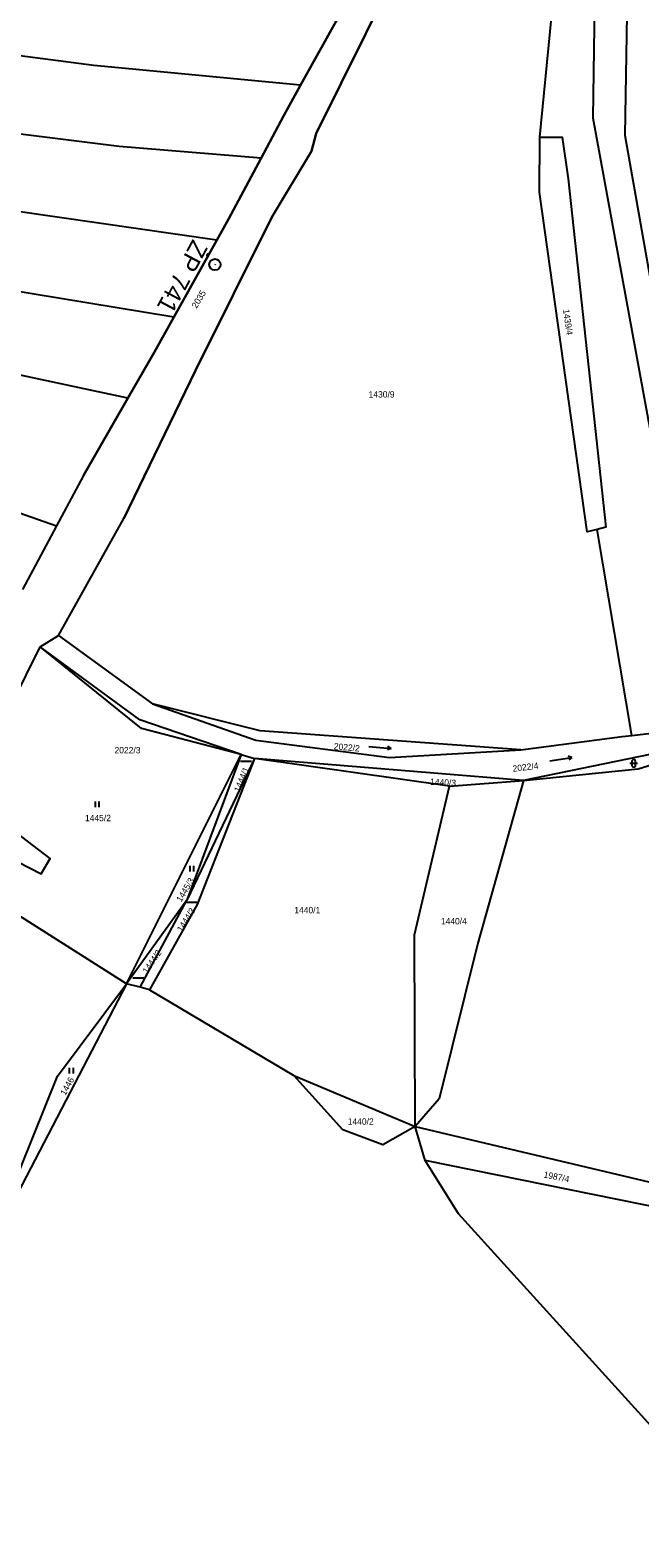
# Model space of a CAD drawing. Extents: x -793666 to -785424, y -1118958 to -1108761.
# Drawn here: x -787242.9 to -787079.7, y -1118708.9 to -1118305 of the extents above; entities that cross this region are included whole.
import ezdxf

# ---------------------------------------------------------------- set-up
doc = ezdxf.new("R2010")
doc.units = 0
for name, color, linetype in [('Hranice parcel', 7, 'Continuous'), ('Parcelní čísla', 7, 'Continuous'), ('Vrstva 53', 7, 'Continuous'), ('Vrstva 63', 7, 'Continuous'), ('Značky kultur', 7, 'Continuous')]:
    doc.layers.add(name, color=color, linetype=linetype)

msp = doc.modelspace()

# ---------------------------------------------------------------- linework, layer by layer
at = {"layer": 'Hranice parcel'}
for p, q in [((-787160.15, -1118301.02), (-787170.53, -1118319.75)), ((-787192.93, -1118361.27), (-787204.45, -1118381.96)), ((-787235.84, -1118437.8), (-787245.01, -1118454.92)), ((-787081.87, -1118493.99), (-787091.16, -1118438.76)), ((-787240.28, -1118470.25), (-787235.39, -1118467.18)), ((-787235.39, -1118467.18), (-787210.21, -1118485.49)), ((-787081.87, -1118493.99), (-787062.37, -1118491.63)), ((-787053.4, -1118494.16), (-787110.85, -1118506.06)), ((-787217.11, -1118560.49), (-787186.43, -1118499.08)), ((-787186.43, -1118499.08), (-787200.96, -1118538.1)), ((-787182.84, -1118500.19), (-787200.96, -1118538.1)), ((-787186.43, -1118499.08), (-787182.84, -1118500.19)), ((-787110.85, -1118506.06), (-787182.84, -1118500.19)), ((-787130.65, -1118507.57), (-787182.84, -1118500.19)), ((-787130.65, -1118507.57), (-787110.85, -1118506.06)), ((-787200.96, -1118538.1), (-787217.11, -1118560.49)), ((-787213.48, -1118561.45), (-787200.96, -1118538.1)), ((-787217.11, -1118560.49), (-787255.19, -1118633.7)), ((-787213.48, -1118561.45), (-787217.11, -1118560.49)), ((-787210.97, -1118562.12), (-787213.48, -1118561.45)), ((-787210.97, -1118562.12), (-787172.32, -1118585.11)), ((-787172.32, -1118585.11), (-787139.82, -1118598.75)), ((-787139.82, -1118598.75), (-787071.98, -1118614.82)), ((-787137.18, -1118607.84), (-787139.82, -1118598.75)), ((-787072.89, -1118620.93), (-787137.18, -1118607.84)), ((-787128.21, -1118622.13), (-787137.18, -1118607.84))]:
    msp.add_line(p, q, dxfattribs=at)
for points in [[(-787177.84, -1117853.72), (-787161.21, -1117872.93), (-787128.04, -1117934.59), (-787083.58, -1118004.78), (-787073.62, -1118057.71), (-787080.45, -1118134.14), (-787083.67, -1118333.2), (-787055.86, -1118490.84)], [(-787163.99, -1117893.46), (-787091.23, -1118006.46), (-787082.09, -1118056.11), (-787089.51, -1118139.72), (-787092.27, -1118328.55), (-787062.37, -1118491.63)], [(-787106.5, -1118333.7), (-787102.87, -1118297.16), (-787097.88, -1118167.47), (-787100.77, -1118148.47)], [(-787235.39, -1118467.18), (-787217.86, -1118435.86), (-787198.68, -1118396.25), (-787178.21, -1118355.17), (-787167.59, -1118337.44), (-787166.34, -1118332.73), (-787139.65, -1118278.87), (-787126.72, -1118247.35), (-787118.12, -1118220.15), (-787109.78, -1118187.27)], [(-787170.53, -1118319.75), (-787225.85, -1118314.51), (-787280.62, -1118307.34), (-787400.74, -1118288.44)], [(-787181.11, -1118339.31), (-787219.07, -1118336.16), (-787286.38, -1118327.77), (-787404, -1118309.48)], [(-787170.53, -1118319.75), (-787175.05, -1118327.91), (-787181.11, -1118339.31)], [(-787192.93, -1118361.27), (-787256.87, -1118352.13), (-787407.09, -1118331.67)], [(-787091.16, -1118438.76), (-787093.84, -1118439.41), (-787106.57, -1118348.47), (-787106.5, -1118333.7)], [(-787106.5, -1118333.7), (-787100.5, -1118333.72), (-787098.9, -1118344.83), (-787088.78, -1118438.18), (-787091.16, -1118438.76)], [(-787181.11, -1118339.31), (-787189.82, -1118355.68), (-787192.93, -1118361.27)], [(-787204.45, -1118381.96), (-787288.56, -1118368.12), (-787409.24, -1118346.36)], [(-787216.75, -1118403.66), (-787289.04, -1118388.21), (-787411.56, -1118360.49)], [(-787204.45, -1118381.96), (-787209.71, -1118391.41), (-787216.75, -1118403.66)], [(-787353.01, -1118397.09), (-787249.07, -1118433.2), (-787235.84, -1118437.8)], [(-787216.75, -1118403.66), (-787228.62, -1118424.3), (-787235.84, -1118437.8)], [(-787256.27, -1118512.79), (-787251.49, -1118492.81), (-787240.28, -1118470.25)], [(-787186.43, -1118499.08), (-787213.6, -1118489.81), (-787240.28, -1118470.25)], [(-787186.43, -1118499.08), (-787213.08, -1118492.14), (-787240.28, -1118470.25)], [(-787111.53, -1118497.85), (-787181.36, -1118492.77), (-787210.21, -1118485.49)], [(-787210.21, -1118485.49), (-787182.49, -1118495.22), (-787146.75, -1118499.9), (-787111.53, -1118497.85)], [(-787111.53, -1118497.85), (-787084.45, -1118494.3), (-787081.87, -1118493.99)], [(-787182.84, -1118500.19), (-787198.25, -1118539.29), (-787210.97, -1118562.12)], [(-787110.85, -1118506.06), (-787080.17, -1118502.89), (-787061.63, -1118497.17)], [(-787139.82, -1118598.75), (-787140.02, -1118547.36), (-787130.65, -1118507.57)], [(-787110.85, -1118506.06), (-787123.11, -1118549.59), (-787133.46, -1118591.34), (-787139.82, -1118598.75)], [(-787264.16, -1118518.6), (-787240, -1118531.03), (-787237.55, -1118526.92), (-787256.27, -1118512.79)], [(-787217.11, -1118560.49), (-787246.95, -1118541.62), (-787266.06, -1118527.5)], [(-787255.19, -1118633.7), (-787235.57, -1118585.27), (-787217.11, -1118560.49)], [(-787139.82, -1118598.75), (-787148.47, -1118603.68), (-787159.24, -1118599.65), (-787172.32, -1118585.11)], [(-787027.23, -1118708.95), (-787062.64, -1118694.47), (-787128.21, -1118622.13)]]:
    msp.add_lwpolyline(points, dxfattribs=at)
at = {"layer": 'Vrstva 53'}
for points in [[(-787140.05, -1117937.14), (-787131.85, -1117955.61), (-787118.45, -1117994.16), (-787110.44, -1118024.18), (-787104.5, -1118053.26), (-787101.82, -1118076.58), (-787101.49, -1118109.72), (-787102.99, -1118131.07), (-787104.86, -1118157.23), (-787109.78, -1118187.27), (-787118.12, -1118220.15), (-787126.72, -1118247.35), (-787139.65, -1118278.87), (-787166.34, -1118332.73), (-787167.59, -1118337.44), (-787178.21, -1118355.17), (-787198.68, -1118396.25), (-787217.86, -1118435.86)], [(-787228.62, -1118424.3), (-787216.75, -1118403.66), (-787209.71, -1118391.41), (-787204.45, -1118381.96), (-787192.93, -1118361.27), (-787189.82, -1118355.68), (-787181.11, -1118339.31), (-787175.05, -1118327.91), (-787170.53, -1118319.75), (-787160.15, -1118301.02)]]:
    msp.add_lwpolyline(points, dxfattribs=at)
at = {"layer": 'Vrstva 63'}
msp.add_line((-787193.42, -1118367.73), (-787193.51, -1118367.91), dxfattribs=at)
msp.add_circle((-787193.46, -1118367.82), 1.51, dxfattribs=at)
at = {"layer": 'Značky kultur'}
for p, q in [((-787152.22, -1118496.92), (-787146.24, -1118497.44)), ((-787146.24, -1118497.44), (-787147.18, -1118496.86)), ((-787186.65, -1118500.86), (-787183.65, -1118500.86)), ((-787146.24, -1118497.44), (-787147.26, -1118497.86)), ((-787103.79, -1118500.81), (-787097.86, -1118499.88)), ((-787097.86, -1118499.88), (-787098.9, -1118499.53)), ((-787097.86, -1118499.88), (-787098.74, -1118500.53)), ((-787081.84, -1118500.94), (-787081.84, -1118501.94)), ((-787080.84, -1118501.94), (-787080.84, -1118500.94)), ((-787082.34, -1118501.44), (-787080.34, -1118501.44)), ((-787225.43, -1118513.19), (-787225.43, -1118511.69)), ((-787224.43, -1118513.19), (-787224.43, -1118511.69)), ((-787200.13, -1118530.41), (-787200.13, -1118528.91)), ((-787199.13, -1118530.41), (-787199.13, -1118528.91)), ((-787201.13, -1118538.67), (-787198.13, -1118538.67)), ((-787215.48, -1118558.92), (-787212.48, -1118558.92)), ((-787232.36, -1118584.56), (-787232.36, -1118583.06)), ((-787231.36, -1118584.56), (-787231.36, -1118583.06))]:
    msp.add_line(p, q, dxfattribs=at)
for centre, start, end in [((-787081.34, -1118500.94), 0, 180), ((-787081.34, -1118501.94), 180, 359.9879)]:
    msp.add_arc(centre, 0.5, start, end, dxfattribs=at)

# ---------------------------------------------------------------- texts
at = {"layer": 'Parcelní čísla'}
for s, rotation, p in [('2035', 59, (-787198.36, -1118379.7)), ('1439/4', 278, (-787100.27, -1118379.91)), ('2022/2', 355, (-787161.69, -1118497.7)), ('1444/1', 68, (-787186.86, -1118509.31)), ('2022/4', 7, (-787113.66, -1118503.73)), ('1440/3', 357, (-787135.89, -1118507.21)), ('1445/3', 59, (-787202.48, -1118538.74)), ('1444/3', 58, (-787202.31, -1118546.76)), ('1444/2', 56, (-787211.55, -1118557.94)), ('1446', 61, (-787233.51, -1118590.57)), ('1987/4', 349, (-787105.57, -1118612.4))]:
    msp.add_text(s, height=1.7, rotation=rotation, dxfattribs=at).set_placement(p)
for s, p in [('1430/9', (-787152.32, -1118403.45)), ('2022/3', (-787220.35, -1118498.77)), ('1445/2', (-787228.26, -1118516.95)), ('1440/1', (-787172.21, -1118541.62)), ('1440/4', (-787132.97, -1118544.59)), ('1440/2', (-787157.91, -1118598.27))]:
    msp.add_text(s, height=1.7, dxfattribs=at).set_placement(p)
at = {"layer": 'Vrstva 63'}
msp.add_text('ŽP 741', height=4.8, rotation=241.8813, dxfattribs=at).set_placement((-787199.39, -1118360.84))

doc.saveas('drawing.dxf')
